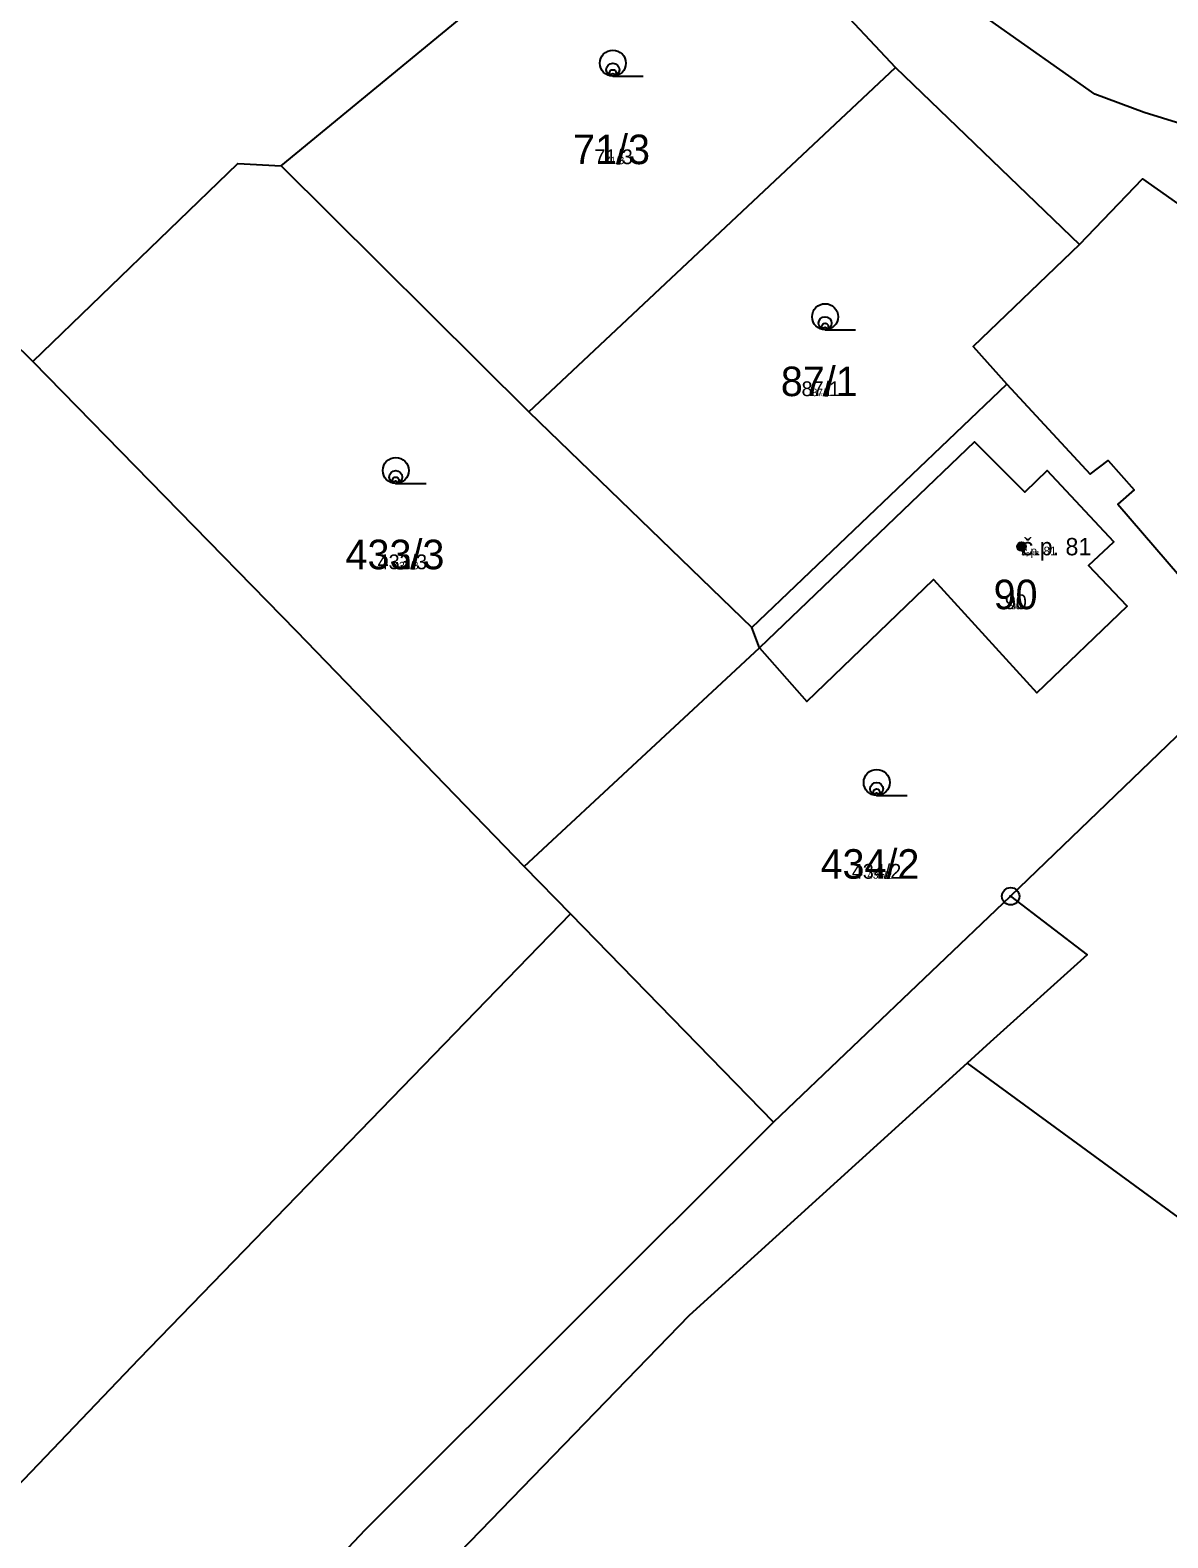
# Model space of a CAD drawing. Extents: x -744652 to -739090, y -980828 to -975855.
# Drawn here: x -742955 to -742889.5, y -978620.9 to -978534.2 of the extents above; entities that cross this region are included whole.
import ezdxf

# ---------------------------------------------------------------- set-up
doc = ezdxf.new("R2010")
doc.units = 0
for name, color, linetype in [('KAT_02_hranice parcel', 7, 'Continuous'), ('KAT_03_1000_st čísla parcelní', 7, 'Continuous'), ('KAT_03_1000_čísla parcelní', 7, 'Continuous'), ('KAT_03_1000_čísla popisná', 7, 'Continuous'), ('KAT_03_100_st čísla parcelní', 7, 'Continuous'), ('KAT_03_100_čísla parcelní', 7, 'Continuous'), ('KAT_03_100_čísla popisná', 7, 'Continuous'), ('KAT_03_250_st čísla parcelní', 7, 'Continuous'), ('KAT_03_250_čísla parcelní', 7, 'Continuous'), ('KAT_03_250_čísla popisná', 7, 'Continuous'), ('KAT_03_500_st čísla parcelní', 7, 'Continuous'), ('KAT_03_500_čísla parcelní', 7, 'Continuous'), ('KAT_03_500_čísla popisná', 7, 'Continuous'), ('KAT_05_1000_značky kultur', 7, 'Continuous'), ('KAT_05_100_značky kultur', 7, 'Continuous'), ('KAT_05_250_značky kultur', 7, 'Continuous'), ('KAT_05_500_značky kultur', 7, 'Continuous'), ('KAT_07_1000_značky budov', 7, 'Continuous'), ('KAT_07_100_značky budov', 7, 'Continuous'), ('KAT_07_500_značky budov', 7, 'Continuous'), ('KAT_11_značky bodu BP', 7, 'Continuous'), ('KAT_14_plocha_budovy', 7, 'Continuous')]:
    doc.layers.add(name, color=color, linetype=linetype)

msp = doc.modelspace()

# ---------------------------------------------------------------- linework, layer by layer
at = {"layer": 'KAT_02_hranice parcel'}
for p, q in [((-742940.59, -978542), (-742917.06, -978522.63)), ((-742911.39, -978529.75), (-742905.22, -978536.33)), ((-742926.34, -978556.16), (-742905.22, -978536.33)), ((-742905.22, -978536.33), (-742894.62, -978546.52)), ((-742940.59, -978542), (-742926.34, -978556.16)), ((-742913.5, -978568.57), (-742898.82, -978554.56)), ((-742926.34, -978556.16), (-742913.5, -978568.57)), ((-742884.6, -978570.54), (-742898.59, -978584.03)), ((-742926.6, -978582.32), (-742923.94, -978585.04)), ((-742912.25, -978597.02), (-742898.59, -978584.03)), ((-742923.94, -978585.04), (-742912.25, -978597.02))]:
    msp.add_line(p, q, dxfattribs=at)
for points in [[(-742887.73, -978539.9), (-742890.9, -978538.92), (-742893.74, -978537.87), (-742899.78, -978533.61)], [(-742966.95, -978540.15), (-742967.55, -978540.81), (-742954.89, -978553.25)], [(-742954.89, -978553.25), (-742943.09, -978541.86), (-742940.59, -978542)], [(-742894.62, -978546.52), (-742891, -978542.75), (-742871.82, -978556.24)], [(-742894.62, -978546.52), (-742900.74, -978552.39), (-742898.82, -978554.56)], [(-742954.89, -978553.25), (-742939.73, -978568.76), (-742926.6, -978582.32)], [(-742898.82, -978554.56), (-742894.02, -978559.74), (-742892.97, -978558.95), (-742891.48, -978560.64), (-742892.41, -978561.47), (-742884.6, -978570.54)], [(-742891.89, -978567.33), (-742894.1, -978565), (-742892.65, -978563.64), (-742896.48, -978559.53), (-742897.78, -978560.78), (-742900.67, -978557.87), (-742913.06, -978569.73), (-742910.33, -978572.82), (-742903.04, -978565.8), (-742897.08, -978572.33), (-742891.89, -978567.33)], [(-742926.6, -978582.32), (-742913.06, -978569.73), (-742913.5, -978568.57)], [(-742898.59, -978584.03), (-742894.18, -978587.39), (-742899.77, -978592.43), (-742901.1, -978593.64)], [(-742923.94, -978585.04), (-742948.79, -978610.67), (-742990.65, -978654.41), (-743049.16, -978715.31)], [(-742901.1, -978593.64), (-742917.1, -978608.16), (-742936.35, -978628), (-742949.7, -978642.34), (-742966.36, -978660.8), (-742998.25, -978696.2)], [(-742901.1, -978593.64), (-742857.07, -978625.79), (-742852.35, -978619.33)], [(-742912.25, -978597.02), (-742935.76, -978620.48), (-742940.39, -978625.39), (-742970.44, -978658.82), (-743000.57, -978689.21), (-743008.61, -978697.49), (-743018.98, -978709.67), (-743024.26, -978713.05)]]:
    msp.add_lwpolyline(points, dxfattribs=at)
at = {"layer": 'KAT_03_1000_čísla popisná'}
msp.add_circle((-742897.96, -978563.91), 0.25, dxfattribs=at)
msp.add_circle((-742897.96, -978563.91), 0.25, dxfattribs=at)
at = {"layer": 'KAT_03_100_čísla popisná'}
msp.add_circle((-742897.96, -978563.91), 0.025, dxfattribs=at)
msp.add_circle((-742897.96, -978563.91), 0.025, dxfattribs=at)
at = {"layer": 'KAT_03_250_čísla popisná'}
msp.add_circle((-742897.96, -978563.91), 0.0625, dxfattribs=at)
msp.add_circle((-742897.96, -978563.91), 0.0625, dxfattribs=at)
at = {"layer": 'KAT_03_500_čísla popisná'}
msp.add_circle((-742897.96, -978563.91), 0.125, dxfattribs=at)
msp.add_circle((-742897.96, -978563.91), 0.125, dxfattribs=at)
at = {"layer": 'KAT_05_1000_značky kultur'}
for p, q in [((-742921.493, -978536.84), (-742919.743, -978536.84)), ((-742909.273, -978551.43), (-742907.523, -978551.43)), ((-742933.993, -978560.28), (-742932.243, -978560.28)), ((-742906.303, -978578.23), (-742904.553, -978578.23))]:
    msp.add_line(p, q, dxfattribs=at)
for centre in [(-742921.493, -978536.09), (-742909.273, -978550.68), (-742933.993, -978559.53), (-742906.303, -978577.48)]:
    msp.add_circle(centre, 0.75, dxfattribs=at)
at = {"layer": 'KAT_05_100_značky kultur'}
for p, q in [((-742921.499, -978536.84), (-742921.324, -978536.84)), ((-742909.279, -978551.43), (-742909.104, -978551.43)), ((-742933.999, -978560.28), (-742933.824, -978560.28)), ((-742906.309, -978578.23), (-742906.134, -978578.23))]:
    msp.add_line(p, q, dxfattribs=at)
for centre in [(-742921.499, -978536.765), (-742909.279, -978551.355), (-742933.999, -978560.205), (-742906.309, -978578.155)]:
    msp.add_circle(centre, 0.075, dxfattribs=at)
at = {"layer": 'KAT_05_250_značky kultur'}
for p, q in [((-742921.498, -978536.84), (-742921.061, -978536.84)), ((-742909.278, -978551.43), (-742908.841, -978551.43)), ((-742933.998, -978560.28), (-742933.561, -978560.28)), ((-742906.308, -978578.23), (-742905.871, -978578.23))]:
    msp.add_line(p, q, dxfattribs=at)
for centre in [(-742921.498, -978536.652), (-742909.278, -978551.242), (-742933.998, -978560.092), (-742906.308, -978578.042)]:
    msp.add_circle(centre, 0.187, dxfattribs=at)
at = {"layer": 'KAT_05_500_značky kultur'}
for p, q in [((-742921.497, -978536.84), (-742920.622, -978536.84)), ((-742909.277, -978551.43), (-742908.402, -978551.43)), ((-742933.997, -978560.28), (-742933.122, -978560.28)), ((-742906.307, -978578.23), (-742905.432, -978578.23))]:
    msp.add_line(p, q, dxfattribs=at)
for centre in [(-742921.496, -978536.465), (-742909.276, -978551.055), (-742933.996, -978559.905), (-742906.306, -978577.855)]:
    msp.add_circle(centre, 0.375, dxfattribs=at)
at = {"layer": 'KAT_07_1000_značky budov'}
msp.add_circle((-742897.967, -978563.909), 0.175, dxfattribs=at)
at = {"layer": 'KAT_07_100_značky budov'}
msp.add_circle((-742897.961, -978563.91), 0.0175, dxfattribs=at)
at = {"layer": 'KAT_07_500_značky budov'}
for centre, radius in [((-742897.963, -978563.91), 0.0875), ((-742897.962, -978563.91), 0.0438)]:
    msp.add_circle(centre, radius, dxfattribs=at)
at = {"layer": 'KAT_11_značky bodu BP'}
for radius in [0.5, 0.0303]:
    msp.add_circle((-742898.59, -978584.03), radius, dxfattribs=at)
at = {"layer": 'KAT_14_plocha_budovy'}
msp.add_lwpolyline([(-742913.06, -978569.73), (-742910.33, -978572.82), (-742903.04, -978565.8), (-742897.08, -978572.33), (-742891.89, -978567.33), (-742894.1, -978565), (-742892.65, -978563.64), (-742896.48, -978559.53), (-742897.78, -978560.78), (-742900.67, -978557.87)], close=True, dxfattribs=at)

# ---------------------------------------------------------------- texts
at = {"layer": 'KAT_03_1000_st čísla parcelní'}
msp.add_text('90', height=1.7, dxfattribs=at).set_placement((-742899.572, -978567.51))
at = {"layer": 'KAT_03_1000_čísla parcelní'}
for s, p in [('71/3', (-742923.781, -978541.9)), ('87/1', (-742911.821, -978555.25)), ('433/3', (-742936.883, -978565.21)), ('434/2', (-742909.533, -978583.02))]:
    msp.add_text(s, height=1.7, dxfattribs=at).set_placement(p)
at = {"layer": 'KAT_03_1000_čísla popisná'}
for s, height, p in [('č.p. 81', 1, (-742897.96, -978564.41)), ('90', 0.017, (-742898.293, -978567.51))]:
    msp.add_text(s, height=height, dxfattribs=at).set_placement(p)
at = {"layer": 'KAT_03_100_st čísla parcelní'}
msp.add_text('90', height=0.17, dxfattribs=at).set_placement((-742898.41, -978567.51))
at = {"layer": 'KAT_03_100_čísla parcelní'}
for s, p in [('71/3', (-742921.583, -978541.9)), ('87/1', (-742909.677, -978555.25)), ('433/3', (-742933.558, -978565.21)), ('434/2', (-742906.299, -978583.02))]:
    msp.add_text(s, height=0.17, dxfattribs=at).set_placement(p)
at = {"layer": 'KAT_03_100_čísla popisná'}
for s, height, p in [('č.p. 81', 0.1, (-742897.96, -978564.41)), ('90', 0.0017, (-742898.282, -978567.51))]:
    msp.add_text(s, height=height, dxfattribs=at).set_placement(p)
at = {"layer": 'KAT_03_250_st čísla parcelní'}
msp.add_text('90', height=0.425, dxfattribs=at).set_placement((-742898.603, -978567.51))
at = {"layer": 'KAT_03_250_čísla parcelní'}
for s, p in [('71/3', (-742921.949, -978541.9)), ('87/1', (-742910.034, -978555.25)), ('433/3', (-742934.112, -978565.21)), ('434/2', (-742906.838, -978583.02))]:
    msp.add_text(s, height=0.425, dxfattribs=at).set_placement(p)
at = {"layer": 'KAT_03_250_čísla popisná'}
for s, height, p in [('č.p. 81', 0.25, (-742897.96, -978564.41)), ('90', 0.00425, (-742898.284, -978567.51))]:
    msp.add_text(s, height=height, dxfattribs=at).set_placement(p)
at = {"layer": 'KAT_03_500_st čísla parcelní'}
msp.add_text('90', height=0.85, dxfattribs=at).set_placement((-742898.926, -978567.51))
at = {"layer": 'KAT_03_500_čísla parcelní'}
for s, p in [('71/3', (-742922.56, -978541.9)), ('87/1', (-742910.63, -978555.25)), ('433/3', (-742935.036, -978565.21)), ('434/2', (-742907.736, -978583.02))]:
    msp.add_text(s, height=0.85, dxfattribs=at).set_placement(p)
at = {"layer": 'KAT_03_500_čísla popisná'}
for s, height, p in [('č.p. 81', 0.5, (-742897.96, -978564.41)), ('90', 0.0085, (-742898.287, -978567.51))]:
    msp.add_text(s, height=height, dxfattribs=at).set_placement(p)

doc.saveas('drawing.dxf')
